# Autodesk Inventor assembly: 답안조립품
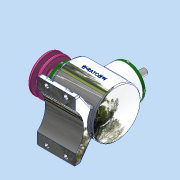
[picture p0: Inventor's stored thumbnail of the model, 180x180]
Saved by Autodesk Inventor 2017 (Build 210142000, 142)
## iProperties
Part Number: 답안조립품
Material: 일반
Document SubType Name: Assembly
Designer: MRC
Author: MRC
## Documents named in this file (17)
- C:\Users\MRC\Desktop\730108V1005\답안조립품.iam
- C:\Users\MRC\Desktop\730108V1005\V-벨트풀리.ipt
- C:\Users\MRC\Desktop\730108V1005\메인 베벨기어.ipt
- C:\Users\MRC\Desktop\730108V1005\메인 축.ipt
- 메인 축.ipt
- C:\Users\MRC\Desktop\730108V1005\베어링 6203.ipt
- C:\Users\MRC\Desktop\730108V1005\본체.ipt
- C:\Users\MRC\Desktop\730108V1005\볼트 M4 x 10.ipt
- C:\Users\MRC\Desktop\730108V1005\서브 베벨기어.ipt
- C:\Users\MRC\Desktop\730108V1005\서브 축.ipt
- 서브 축.ipt
- C:\Users\MRC\Desktop\730108V1005\오일실 17 x 32 x 8.ipt
- C:\Users\MRC\Desktop\730108V1005\와셔 4 x 16.ipt
- C:\Users\MRC\Desktop\730108V1005\육각볼트 M4 x 8.ipt
- C:\Users\MRC\Desktop\730108V1005\커버.ipt
- C:\Users\MRC\Desktop\730108V1005\키 4 x 4 x 14.ipt
- C:\Users\MRC\Desktop\730108V1005\키 5 x 5 x 14.ipt
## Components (1 placed, 1 different names)
1. V-벨트풀리:1
